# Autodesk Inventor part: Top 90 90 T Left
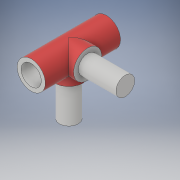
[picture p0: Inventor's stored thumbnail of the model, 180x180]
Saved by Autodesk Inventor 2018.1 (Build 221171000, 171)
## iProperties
Created: 2018-06
Part Number: Top 90 90 T Left
Material: Generic
Document SubType Name: Modeling
Designer: Ryan
Density: 1 g/cm^3
Appearance: Default
Author: Ryan
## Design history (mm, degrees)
derived "Assembly3 Part out.iam"
sketch "Sketch1"
  geometry: L1 (-38.527, 77.015)-(136.232, 77.015); L2 (136.232, 77.015)-(136.232, -217.058); L3 (136.232, -217.058)-(-38.527, -217.058); L4 (-38.527, -217.058)-(-38.527, 77.015); 1 further point
  constraints: 8 end point, 2 parallel, 1 horizontal, 1 perpendicular
extrude "Extrusion1" cut sketch "Sketch1" distance "d1" = 25.4; taper "d2" = 0 deg
workplane "Work Plane2"
  workplane "Work Plane1"
workpoint "Work Point1"
workplane "Work Plane3"
workplane "Work Plane4"
workplane "Work Plane5"
workplane "Work Plane6"
workplane "Work Plane7"
workplane "Work Plane8"
workplane "Work Plane9"
workplane "Work Plane10"
workplane "Work Plane11"
workplane "Work Plane12"
sketch "Sketch2"
  geometry: L1 (-186.77, 38.249)-(76.849, 38.249); L2 (76.849, 38.249)-(76.849, -126.593); L3 (76.849, -126.593)-(-186.77, -126.593); L4 (-186.77, -126.593)-(-186.77, 38.249); 1 further point
  constraints: 8 end point, 2 parallel, 1 horizontal, 1 perpendicular
extrude "Extrusion2" cut sketch "Sketch2" distance "d10" = 255.5875; taper "d11" = 0 deg
sketch "Sketch3"
  geometry: L1 (-118.781, 34.401)-(30.026, 34.401); L2 (30.026, 34.401)-(30.026, -118.896); L3 (30.026, -118.896)-(-118.781, -118.896); L4 (-118.781, -118.896)-(-118.781, 34.401); 1 further point
  constraints: 8 end point, 2 parallel, 1 horizontal, 1 perpendicular
extrude "Extrusion3" cut sketch "Sketch3" distance "d12" = 255.5875; taper "d13" = 0 deg
sketch "Sketch4"
  geometry: L1 (218.809, 34.128)-(50.76, 34.128); L2 (50.76, 34.128)-(50.76, -112.113); L3 (50.76, -112.113)-(218.809, -112.113); L4 (218.809, -112.113)-(218.809, 34.128); 1 further point
  constraints: 8 end point, 2 parallel, 1 horizontal, 1 perpendicular
extrude "Extrusion4" cut sketch "Sketch4" stored distance "d14" = 255.5875; taper "d15" = 0 deg
sketch "Sketch5"
  geometry: L1 (-123.912, -23.452)-(16.556, -23.452); L2 (16.556, -23.452)-(16.556, 25.295); L3 (16.556, 25.295)-(-123.912, 25.295); L4 (-123.912, 25.295)-(-123.912, -23.452); 1 further point
  constraints: 8 end point, 2 parallel, 1 horizontal, 1 perpendicular
extrude "Extrusion5" cut sketch "Sketch5" distance "d16" = 255.5875; taper "d17" = 0 deg
sketch "Sketch6"
  geometry: C1 r 3.429 at (0, 0); C2 r 3.429 at (101.6, 0); A1 r 4.763 centre (0, 0) between (-4.762, 0) and (3.368, -3.368) reference; A2 r 4.762 centre (101.6, 0) between (98.232, -3.368) and (106.362, 0) reference; 1 further point
  constraints: 2 centre point, 2 coincident
  dimensions: "d18" = 6.858 diameter of C1; "d19" = 6.858 diameter of C2
extrude "Extrusion6" cut sketch "Sketch6" distance "d20" = 255.5875; taper "d21" = 0 deg
workplane "Work Plane13"
workplane "Work Plane14"
sketch "Sketch7"
  geometry: L1 (-14.927, 11.967)-(19.631, 11.967); L2 (19.631, 11.967)-(19.631, -10.679); L3 (19.631, -10.679)-(-14.927, -10.679); L4 (-14.927, -10.679)-(-14.927, 11.967); 1 further point
  constraints: 8 end point, 2 parallel, 1 horizontal, 1 perpendicular
extrude "Extrusion7" cut sketch "Sketch7" stored distance "d24" = 255.5875; taper "d25" = 0 deg
sketch "Sketch8"
  geometry: C1 r 4.763 at (0, 0) reference; C2 r 3.175 at (0, 0); 1 further point
  constraints: 1 centre point, 1 coincident
  dimensions: "d26" = 6.35 diameter of C2
extrude "Extrusion8" join sketch "Sketch8" distance "d27" = 12.7; taper "d28" = 0 deg
workplane "Work Plane15"
sketch "Sketch9"
  geometry: L1 (-11.824, 12.427)-(116.114, 12.427); L2 (116.114, 12.427)-(116.114, -14.631); L3 (116.114, -14.631)-(-11.824, -14.631); L4 (-11.824, -14.631)-(-11.824, 12.427); 1 further point
  constraints: 8 end point, 2 parallel, 1 horizontal, 1 perpendicular
extrude "Extrusion9" cut sketch "Sketch9" distance "d30" = 12.7; taper "d31" = 0 deg
sketch "Sketch10"
  geometry: L1 (0, 0)-(4.762, -4.762) reference; C1 r 3.175 at (0, 0); C2 r 3.175 at (101.6, 0); A1 r 4.762 centre (101.6, 0) between (98.232, -3.368) and (106.362, 0) reference; 2 further points
  constraints: 2 centre point, 1 coincident
  dimensions: "d32" = 6.35 diameter of C1; "d33" = 6.35 diameter of C2
extrude "Extrusion10" join sketch "Sketch10" distance "d34" = 12.7; taper "d35" = 0 deg
sketch "Sketch11"
  geometry: C1 r 4.763 at (0, 0) reference; C2 r 3.175 at (0, 0); 1 further point
  constraints: 1 centre point, 1 coincident
  dimensions: "d36" = 6.35 diameter of C2
extrude "Extrusion11" join sketch "Sketch11" distance "d37" = 12.7; taper "d38" = 0 deg
sketch "Sketch12"
  geometry: C1 r 27.467 at (-2.984, 0.812); 1 further point
  constraints: 1 centre point
extrude "Extrusion12" cut sketch "Sketch12" distance "d39" = 104.775; taper "d40" = 0 deg
body "Solid1"
node "Rov v4.2.ipt:1" dims "d0" = 10
node "Motor mount.ipt:1" dims "d0" = 10
node "Motor mount.ipt:2" dims "d0" = 10
node "Motor mount_MIR2.ipt:1" dims "d0" = 10
other parameters: "d3" = 12.7, "d4" = 12.7, "d5" = -12.7, "d6" = 12.7, "d7" = -12.7, "d8" = 12.7, "d9" = -12.7, "d22" = -6.35, "d23" = -6.35, "d29" = -6.35
